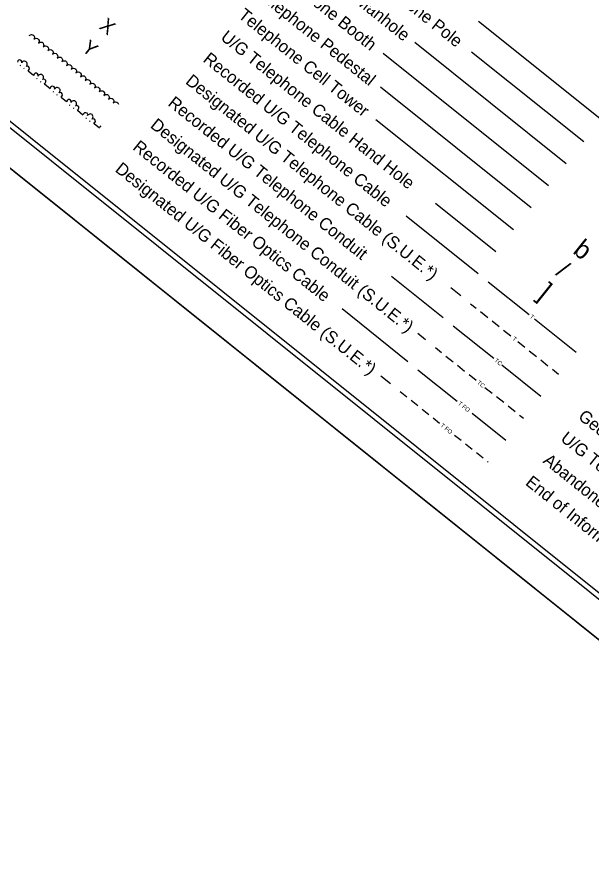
# Model space of a CAD drawing. Extents: x 1730256 to 1738218, y 910410 to 917906.
# Drawn here: x 1732282 to 1733099, y 911533 to 912757 of the extents above; entities that cross this region are included whole.
import ezdxf

# ---------------------------------------------------------------- set-up
doc = ezdxf.new("R2010")
doc.units = 0
for name, color, linetype in [('Sheet Cutting Line CELL', 7, 'Continuous'), ('Sheet Plot Border Inside CELL', 7, 'Continuous'), ('Sheet Plot Border Outside CELL', 7, 'Continuous'), ('Sheet Symbology CELL', 7, 'Continuous')]:
    doc.layers.add(name, color=color, linetype=linetype)

msp = doc.modelspace()

# ---------------------------------------------------------------- linework, layer by layer
at = {"layer": 'Sheet Cutting Line CELL'}
msp.add_line((1730903.7, 913637.3), (1733533.3, 911532.8), dxfattribs=at)
at = {"layer": 'Sheet Plot Border Inside CELL'}
msp.add_lwpolyline([(1730952, 913656.1), (1733554.3, 911573.5), (1734872.8, 913221.1), (1732270.6, 915303.6)], close=True, dxfattribs=at)
at = {"layer": 'Sheet Plot Border Outside CELL'}
msp.add_lwpolyline([(1730903.7, 913637.3), (1733533.3, 911532.8), (1734907.9, 913250.5), (1732278.3, 915354.9)], close=True, dxfattribs=at)
at = {"layer": 'Sheet Symbology CELL'}
for p, q in [((1733112.2, 912610.9), (1732937.5, 912750.8)), ((1732298.8, 912730.8), (1732300.5, 912731.9)), ((1732300.5, 912731.9), (1732302.2, 912732.2)), ((1732302.2, 912732.2), (1732304.1, 912731.9)), ((1732304.1, 912731.9), (1732305.5, 912730.7)), ((1732305.5, 912730.7), (1732306.2, 912728.9)), ((1732306.2, 912727.2), (1732305.5, 912725.6)), ((1732305.5, 912725.5), (1732307.1, 912726.6)), ((1732306.2, 912728.9), (1732306.2, 912727.2)), ((1732307.1, 912726.6), (1732308.9, 912726.9)), ((1732308.9, 912726.9), (1732310.7, 912726.6)), ((1732310.7, 912726.6), (1732312.2, 912725.4)), ((1732312.8, 912721.9), (1732312.1, 912720.3)), ((1732312.2, 912725.4), (1732312.8, 912723.6)), ((1732312.8, 912723.6), (1732312.8, 912721.9)), ((1732313.8, 912721.3), (1732315.5, 912721.5)), ((1732315.5, 912721.5), (1732317.3, 912721.2)), ((1732312.1, 912720.2), (1732313.8, 912721.3)), ((1732317.3, 912721.2), (1732318.8, 912720.1)), ((1732319.5, 912716.6), (1732318.7, 912715)), ((1732318.7, 912714.9), (1732320.4, 912716)), ((1732318.8, 912720.1), (1732319.4, 912718.3)), ((1732319.4, 912718.3), (1732319.5, 912716.6)), ((1732320.4, 912716), (1732322.2, 912716.2)), ((1732322.2, 912716.2), (1732324, 912715.9)), ((1732324, 912715.9), (1732325.4, 912714.7)), ((1732325.4, 912714.7), (1732326.1, 912713)), ((1732326.1, 912711.3), (1732325.4, 912709.7)), ((1732325.4, 912709.5), (1732327, 912710.7)), ((1732326.1, 912713), (1732326.1, 912711.3)), ((1732327, 912710.7), (1732328.8, 912710.9)), ((1732328.8, 912710.9), (1732330.6, 912710.6)), ((1732330.6, 912710.6), (1732332.1, 912709.4)), ((1732332.1, 912709.4), (1732332.7, 912707.7)), ((1733062.2, 912548.5), (1732846.9, 912720.8)), ((1732332.8, 912706), (1732332, 912704.4)), ((1732332, 912704.2), (1732333.7, 912705.3)), ((1732332.7, 912707.7), (1732332.8, 912706)), ((1732333.7, 912705.3), (1732335.4, 912705.6)), ((1732335.4, 912705.6), (1732337.2, 912705.3)), ((1732337.2, 912705.3), (1732338.7, 912704.1)), ((1732339.4, 912700.6), (1732338.6, 912699.1)), ((1732338.7, 912704.1), (1732339.3, 912702.3)), ((1732338.7, 912698.9), (1732340.3, 912700)), ((1732339.3, 912702.3), (1732339.4, 912700.6)), ((1732340.3, 912700), (1732342.1, 912700.3)), ((1732342.1, 912700.3), (1732343.9, 912700)), ((1732343.9, 912700), (1732345.4, 912698.8)), ((1732345.4, 912698.8), (1732346, 912697)), ((1732346, 912697), (1732346, 912695.3)), ((1733037.2, 912517.3), (1732802.2, 912705.3)), ((1733087.2, 912579.7), (1732927.8, 912707.3)), ((1732285.6, 912688.8), (1732286.4, 912688.2)), ((1732346, 912695.3), (1732345.3, 912693.8)), ((1732345.3, 912693.6), (1732346.9, 912694.7)), ((1732346.9, 912694.7), (1732348.7, 912695)), ((1732348.7, 912695), (1732350.5, 912694.7)), ((1732350.5, 912694.7), (1732352, 912693.5)), ((1732352.7, 912690), (1732351.9, 912688.4)), ((1732351.9, 912688.3), (1732353.6, 912689.4)), ((1732352, 912693.5), (1732352.6, 912691.7)), ((1732352.6, 912691.7), (1732352.7, 912690)), ((1732353.6, 912689.4), (1732355.3, 912689.7)), ((1732355.3, 912689.7), (1732357.1, 912689.4)), ((1732357.1, 912689.4), (1732358.6, 912688.2)), ((1732359.3, 912684.7), (1732358.5, 912683.1)), ((1732358.6, 912688.2), (1732359.3, 912686.4)), ((1732359.3, 912686.4), (1732359.3, 912684.7)), ((1732291.1, 912684.5), (1732291.9, 912683.8)), ((1732297.3, 912680.8), (1732305.1, 912674.6)), ((1732358.6, 912683), (1732360.2, 912684.1)), ((1732360.2, 912684.1), (1732362, 912684.4)), ((1732362, 912684.4), (1732363.8, 912684.1)), ((1732363.8, 912684.1), (1732365.3, 912682.9)), ((1732365.9, 912679.4), (1732365.2, 912677.8)), ((1732365.2, 912677.7), (1732366.9, 912678.8)), ((1732365.3, 912682.9), (1732365.9, 912681.1)), ((1732365.9, 912681.1), (1732365.9, 912679.4)), ((1732366.9, 912678.8), (1732368.6, 912679.1)), ((1732368.6, 912679.1), (1732370.4, 912678.8)), ((1732370.4, 912678.8), (1732371.9, 912677.6)), ((1732372.6, 912674.1), (1732371.8, 912672.5)), ((1732371.8, 912672.4), (1732373.5, 912673.5)), ((1732371.9, 912677.6), (1732372.5, 912675.8)), ((1732372.5, 912675.8), (1732372.6, 912674.1)), ((1732373.5, 912673.5), (1732375.2, 912673.7)), ((1732375.2, 912673.7), (1732377.1, 912673.4)), ((1732377.1, 912673.4), (1732378.5, 912672.3)), ((1732309.1, 912670.1), (1732309.8, 912669.5)), ((1732314.5, 912665.7), (1732315.3, 912665.1)), ((1732320.7, 912662.1), (1732328.5, 912655.8)), ((1732378.5, 912672.3), (1732379.2, 912670.5)), ((1732379.2, 912668.8), (1732378.5, 912667.2)), ((1732378.5, 912667.1), (1732380.1, 912668.2)), ((1732379.2, 912670.5), (1732379.2, 912668.8)), ((1732380.1, 912668.2), (1732381.9, 912668.4)), ((1732381.9, 912668.4), (1732383.7, 912668.1)), ((1732383.7, 912668.1), (1732385.2, 912666.9)), ((1732385.8, 912663.5), (1732385.1, 912661.9)), ((1732385.1, 912661.7), (1732386.8, 912662.9)), ((1732385.2, 912666.9), (1732385.8, 912665.2)), ((1732385.8, 912665.2), (1732385.8, 912663.5)), ((1732386.8, 912662.9), (1732388.5, 912663.1)), ((1732388.5, 912663.1), (1732390.3, 912662.8)), ((1732390.3, 912662.8), (1732391.8, 912661.6)), ((1732391.8, 912661.6), (1732392.4, 912659.9)), ((1732332.5, 912651.4), (1732333.3, 912650.7)), ((1732392.5, 912658.2), (1732391.7, 912656.6)), ((1732391.7, 912656.4), (1732393.4, 912657.5)), ((1732392.4, 912659.9), (1732392.5, 912658.2)), ((1732393.4, 912657.5), (1732395.2, 912657.8)), ((1732395.2, 912657.8), (1732397, 912657.5)), ((1732397, 912657.5), (1732398.4, 912656.3)), ((1732398.4, 912656.3), (1732399.1, 912654.5)), ((1732399.1, 912652.8), (1732398.4, 912651.3)), ((1732398.4, 912651.1), (1732400, 912652.2)), ((1732399.1, 912654.5), (1732399.1, 912652.8)), ((1732400, 912652.2), (1732401.8, 912652.5)), ((1732401.8, 912652.5), (1732403.6, 912652.2)), ((1732403.6, 912652.2), (1732405.1, 912651)), ((1732405.1, 912651), (1732405.7, 912649.2)), ((1732405.7, 912649.2), (1732405.8, 912647.5)), ((1733012.2, 912486), (1732798, 912657.4)), ((1732337.9, 912647), (1732338.7, 912646.4)), ((1732344.1, 912643.3), (1732351.9, 912637.1)), ((1732405.8, 912647.5), (1732405, 912646)), ((1732405, 912645.8), (1732406.7, 912646.9)), ((1732406.7, 912646.9), (1732408.4, 912647.2)), ((1732408.4, 912647.2), (1732410.2, 912646.9)), ((1732410.2, 912646.9), (1732411.7, 912645.7)), ((1732412.4, 912642.2), (1732411.6, 912640.6)), ((1732411.7, 912645.7), (1732412.3, 912643.9)), ((1732411.7, 912640.5), (1732413.3, 912641.6)), ((1732412.3, 912643.9), (1732412.4, 912642.2)), ((1732413.3, 912641.6), (1732415.1, 912641.9)), ((1732415.1, 912641.9), (1732416.9, 912641.6)), ((1732416.9, 912641.6), (1732418.4, 912640.4)), ((1732419, 912636.9), (1732418.3, 912635.3)), ((1732418.3, 912635.2), (1732419.9, 912636.3)), ((1732418.4, 912640.4), (1732419, 912638.6)), ((1732419, 912638.6), (1732419, 912636.9)), ((1732419.9, 912636.3), (1732421.7, 912636.6)), ((1732421.7, 912636.6), (1732423.5, 912636.3)), ((1732423.5, 912636.3), (1732425, 912635.1)), ((1732355.9, 912632.6), (1732356.7, 912632)), ((1732361.4, 912628.2), (1732362.1, 912627.6)), ((1732367.5, 912624.6), (1732375.3, 912618.3)), ((1732425, 912635.1), (1732425.6, 912633.3)), ((1732425.6, 912633.3), (1732425.6, 912633.2)), ((1732379.3, 912613.9), (1732380.1, 912613.2)), ((1732987.2, 912454.8), (1732791.7, 912611.3)), ((1732384.8, 912609.5), (1732385.6, 912608.9)), ((1732391, 912605.8), (1732398.8, 912599.6)), ((1732962.2, 912423.6), (1732876.3, 912492.3)), ((1732937.2, 912392.3), (1732834.9, 912474.3)), ((1732887.2, 912329.9), (1732814, 912388.5)), ((1732951.3, 912381.1), (1733009.3, 912334.7)), ((1732912.2, 912361.1), (1732898, 912372.5)), ((1732837.3, 912267.4), (1732743.5, 912342.4)), ((1732926.3, 912349.8), (1732934.2, 912343.6)), ((1732940.4, 912338.6), (1732950.6, 912330.4)), ((1732901.3, 912318.6), (1732959.2, 912272.3)), ((1732956.8, 912325.4), (1732967, 912317.3)), ((1733017.1, 912328.4), (1733076.2, 912281.1)), ((1732862.3, 912298.6), (1732851.2, 912307.5)), ((1732973.2, 912312.3), (1732983.4, 912304.2)), ((1732993.3, 912296.2), (1733003.5, 912288.1)), ((1732876.3, 912287.4), (1732885.1, 912280.4)), ((1733009.7, 912283.1), (1733019.9, 912275)), ((1732891.3, 912275.4), (1732901.5, 912267.3)), ((1733026.1, 912270), (1733036.3, 912261.8)), ((1732907.7, 912262.3), (1732917.8, 912254.2)), ((1732970.9, 912262.9), (1733026.2, 912218.6)), ((1733042.5, 912256.8), (1733051.2, 912249.9)), ((1732812.3, 912236.2), (1732798.9, 912246.9)), ((1732851.3, 912256.1), (1732907.4, 912211.3)), ((1732924.1, 912249.2), (1732934.2, 912241)), ((1732826.3, 912224.9), (1732835.5, 912217.6)), ((1732946.7, 912231), (1732956.9, 912222.9)), ((1732841.7, 912212.6), (1732851.1, 912205.1)), ((1732963.1, 912217.9), (1732973.3, 912209.8)), ((1732857.3, 912200.1), (1732866.7, 912192.6)), ((1732979.5, 912204.8), (1732989.7, 912196.7)), ((1732872.9, 912187.6), (1732882.3, 912180.1)), ((1732928.4, 912194.4), (1732976.3, 912156.2)), ((1732995.9, 912191.7), (1733001.3, 912187.4)), ((1732903.4, 912163.3), (1732912.8, 912155.8)), ((1732919, 912150.8), (1732928.4, 912143.3)), ((1732934.6, 912138.3), (1732944, 912130.8)), ((1732950.2, 912125.8), (1732951.3, 912124.9))]:
    msp.add_line(p, q, dxfattribs=at)
msp.add_lwpolyline([(1734850.1, 913232.7), (1732507.9, 915107.2), (1731197, 913469.2), (1733539.2, 911594.7)], close=True, dxfattribs=at)
for centre, radius, start, end in [((1732285.2, 912693.1), 3.16, 339.7646, 180.5612), ((1732291.9, 912690.3), 4.12, 307.2934, 155.3659), ((1732296.1, 912684.3), 3.16, 282.0982, 122.8947), ((1732308.6, 912674.3), 3.16, 339.7646, 180.5612), ((1732315.3, 912671.5), 4.12, 307.2934, 155.3659), ((1732319.5, 912665.6), 3.16, 282.0982, 122.8947), ((1732332, 912655.6), 3.16, 339.7646, 180.5612), ((1732338.7, 912652.8), 4.12, 307.2934, 155.3659), ((1732343, 912646.9), 3.16, 282.0982, 122.8947), ((1732355.4, 912636.9), 3.16, 339.7646, 180.5612), ((1732362.2, 912634), 4.12, 307.2934, 155.3659), ((1732366.4, 912628.1), 3.16, 282.0982, 122.8947), ((1732378.9, 912618.1), 3.16, 339.7646, 180.5612), ((1732385.6, 912615.3), 4.12, 307.2934, 155.3659), ((1732389.8, 912609.4), 3.16, 282.0982, 122.8947), ((1732402.3, 912599.4), 3.16, 117.5807, 165.0787)]:
    msp.add_arc(centre, radius, start, end, dxfattribs=at)

# ---------------------------------------------------------------- texts
for s, height, p in [('Proposed Telephone Pole', 17.5, (1732694.7, 912882.2)), ('Telephone Manhole', 17.5, (1732669.7, 912851)), ('Telephone Booth', 17.5, (1732644.7, 912819.7)), ('Telephone Pedestal', 17.5, (1732619.7, 912788.5)), ('Telephone Cell Tower', 17.5, (1732594.8, 912757.3)), ('X', 20, (1732397.2, 912741.7)), ('U/G Telephone Cable Hand Hole', 17.5, (1732569.8, 912726)), ('Y', 20, (1732372.2, 912710.5)), ('Recorded U/G Telephone Cable', 17.5, (1732544.8, 912694.8)), ('Designated U/G Telephone Cable (S.U.E.*)', 17.5, (1732519.8, 912663.6)), ('Recorded U/G Telephone Conduit', 17.5, (1732494.8, 912632.3)), ('Designated U/G Telephone Conduit (S.U.E.*)', 17.5, (1732469.8, 912601.1)), ('Recorded U/G Fiber Optics Cable', 17.5, (1732444.8, 912569.9)), ('Designated U/G Fiber Optics Cable (S.U.E.*)', 17.5, (1732419.8, 912538.6)), ('b', 26.4, (1733070.2, 912422.7)), ('/', 25, (1733046.2, 912391.6)), (']', 27, (1733019.8, 912360.2)), ('T', 6, (1733009.8, 912330.4)), ('T', 6, (1732985, 912299)), ('TC', 6, (1732959.5, 912268.2)), ('TC', 6, (1732934.9, 912236.7)), ('T FO', 6, (1732907.8, 912207.1)), ('Geoenvironmental Boring', 17.5, (1733078, 912187.2)), ('T FO', 6, (1732882.8, 912175.9)), ('U/G Test Hole (S.U.E.*)', 17.5, (1733053, 912156)), ('Abandoned According to Utility Records', 17.5, (1733028, 912124.7)), ('End of Information', 17.5, (1733003, 912093.5))]:
    msp.add_text(s, height=height, rotation=321.3297, dxfattribs=at).set_placement(p)

doc.saveas('drawing.dxf')
